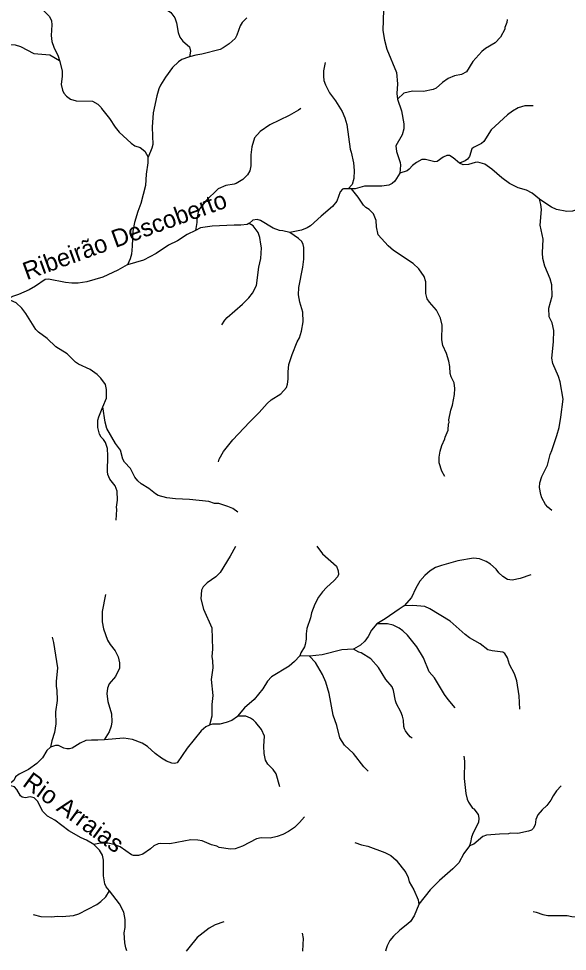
# Model space of a CAD drawing. Extents: x 500 to 555.2, y 9115.7 to 9171.
# Drawn here: x 528.19 to 534.42, y 9115.69 to 9126.27 of the extents above; entities that cross this region are included whole.
import ezdxf
from ezdxf.enums import TextEntityAlignment as Align

# ---------------------------------------------------------------- set-up
doc = ezdxf.new("R2010")
doc.units = 0
doc.header["$LTSCALE"] = 0.064
doc.layers.add('61', color=7, linetype='Continuous')
doc.layers.add('7', color=7, linetype='Continuous', lineweight=25)

msp = doc.modelspace()

# ---------------------------------------------------------------- linework, layer by layer
at = {"layer": '7'}
msp.add_line((531.9688, 9124.34), (531.9304, 9124.3404), dxfattribs=at)
for points in [[(529.3673, 9127.1028), (529.4063, 9127.1229), (529.4402, 9127.1229), (529.4792, 9127.1064), (529.5026, 9127.0847), (529.516, 9127.0636), (529.5298, 9127.004), (529.523, 9126.8054), (529.538, 9126.7218), (529.5514, 9126.6812), (529.5843, 9126.6248), (529.6227, 9126.5758), (529.687, 9126.5131), (529.7188, 9126.494), (529.7656, 9126.4471), (529.9201, 9126.339), (529.9628, 9126.2798), (529.9841, 9126.2226), (530.0006, 9126.1144), (530.0201, 9126.0623), (530.056, 9126.0162), (530.1293, 9125.9499), (530.1415, 9125.9017), (530.1322, 9125.8388)], [(527.3124, 9126.8729), (527.3376, 9126.8303), (527.3752, 9126.7879), (527.4594, 9126.7168), (527.5199, 9126.6335), (527.6458, 9126.514), (527.6924, 9126.4299), (527.7599, 9126.3524), (527.8218, 9126.305), (527.8558, 9126.2711), (527.8955, 9126.2143), (527.9421, 9126.1666), (527.9587, 9126.1564), (527.9813, 9126.129), (528.009, 9126.0495), (528.0386, 9126.0066), (528.0876, 9125.9786), (528.1531, 9125.9727), (528.2133, 9125.9546), (528.3623, 9125.877), (528.544, 9125.86), (528.653, 9125.7947)], [(528.6852, 9126.8448), (528.6686, 9126.8065), (528.633, 9126.7709), (528.5477, 9126.7037), (528.4229, 9126.5503), (528.4093, 9126.5199), (528.4031, 9126.4752), (528.416, 9126.4251), (528.4241, 9126.4208), (528.4489, 9126.385), (528.5422, 9126.2948), (528.5653, 9126.2461), (528.5682, 9126.1995), (528.5605, 9126.0782), (528.5687, 9126.0126), (528.5914, 9125.9477), (528.6392, 9125.8451), (528.653, 9125.7947)], [(532.4206, 9126.6912), (532.4179, 9126.6374), (532.3516, 9126.4503), (532.335, 9126.3716), (532.3266, 9126.1347), (532.3431, 9126.0284), (532.3707, 9125.9247), (532.4793, 9125.6602), (532.4904, 9125.5296), (532.4842, 9125.4203), (532.494, 9125.3578)], [(530.781, 9126.2793), (530.73, 9126.227), (530.7073, 9126.1892), (530.6694, 9126.0843), (530.6476, 9126.0468), (530.581, 9125.9858), (530.514, 9125.9389), (530.4795, 9125.9225), (530.2696, 9125.8667), (530.2019, 9125.8579), (530.1322, 9125.8388)], [(533.7383, 9126.2622), (533.7351, 9126.2273), (533.7124, 9126.1712), (533.7105, 9126.1512), (533.6628, 9126.0591), (533.6027, 9125.9963), (533.4906, 9125.9303), (533.4486, 9125.8994), (533.3474, 9125.7839), (533.2762, 9125.6683), (533.2193, 9125.6373), (533.1402, 9125.6206), (533.0676, 9125.5934), (533.0015, 9125.5473), (532.9294, 9125.4802), (532.8961, 9125.465), (532.7859, 9125.4452), (532.6638, 9125.4482), (532.565, 9125.4239), (532.494, 9125.3578)], [(528.653, 9125.7947), (528.6848, 9125.6786), (528.685, 9125.6197), (528.6754, 9125.5238), (528.6899, 9125.4589), (528.7048, 9125.4255), (528.7337, 9125.3909), (528.7803, 9125.3584), (528.844, 9125.3384), (529.0301, 9125.3332), (529.0919, 9125.299), (529.1273, 9125.2632), (529.1299, 9125.2519), (529.221, 9125.1389), (529.2867, 9125.0389), (529.3335, 9124.982), (529.4684, 9124.8577), (529.5113, 9124.8286), (529.5702, 9124.8073), (529.6245, 9124.7678), (529.6599, 9124.6991)], [(530.1322, 9125.8388), (530.119, 9125.8352), (530.0427, 9125.8055), (530.004, 9125.7797), (529.9362, 9125.7152), (529.8577, 9125.6049), (529.8029, 9125.5155), (529.7838, 9125.474), (529.7597, 9125.3966), (529.7189, 9125.202), (529.7087, 9125.0399), (529.7151, 9124.8422), (529.705, 9124.8014), (529.6599, 9124.6991)], [(531.6715, 9125.7733), (531.6524, 9125.678), (531.6508, 9125.6178), (531.6574, 9125.5698), (531.6756, 9125.52), (531.7204, 9125.4307), (531.7873, 9125.3396), (531.8641, 9125.2164), (531.8934, 9125.1434), (531.9151, 9125.0692), (531.9556, 9124.7905), (531.9671, 9124.7569), (531.9916, 9124.6355), (532.0017, 9124.5462), (531.9952, 9124.455), (531.9759, 9124.3902), (531.9304, 9124.3404)], [(532.494, 9125.3578), (532.5381, 9125.2253), (532.5644, 9125.0777), (532.5628, 9125.0193), (532.5447, 9124.9531), (532.4743, 9124.8274), (532.4815, 9124.7633), (532.5234, 9124.6375), (532.5265, 9124.6079), (532.5184, 9124.5188)], [(531.3933, 9125.2506), (531.3696, 9125.2319), (531.2614, 9125.1709), (531.0416, 9125.0668), (530.9337, 9124.9918), (530.8701, 9124.9183), (530.8389, 9124.8152), (530.8257, 9124.724), (530.8272, 9124.5987), (530.8159, 9124.5451), (530.7908, 9124.4982), (530.7363, 9124.444), (530.6614, 9124.4), (530.6386, 9124.3921), (530.5438, 9124.3785), (530.458, 9124.3387), (530.3151, 9124.2028), (530.2468, 9124.1158), (530.2306, 9124.0764), (530.214, 9123.9925), (530.2154, 9123.9584), (530.1999, 9123.8665)], [(534.0337, 9125.2824), (533.938, 9125.2827), (533.8618, 9125.2581), (533.7963, 9125.222), (533.7405, 9125.1793), (533.5558, 9125.0094), (533.471, 9124.876), (533.4477, 9124.8522), (533.3535, 9124.8079), (533.3375, 9124.7925), (533.3092, 9124.7077), (533.2876, 9124.6742), (533.2615, 9124.6561), (533.1973, 9124.6298)], [(529.6599, 9124.6991), (529.6595, 9124.6983), (529.656, 9124.6334), (529.6382, 9124.5075), (529.6297, 9124.3783), (529.5792, 9124.1729), (529.5437, 9124.0811), (529.5051, 9123.9584), (529.4872, 9123.86), (529.4813, 9123.6888), (529.4727, 9123.5995), (529.4566, 9123.5466), (529.4269, 9123.4774)], [(533.1973, 9124.6298), (533.1241, 9124.6915), (533.083, 9124.7184), (533.052, 9124.7178), (533.0117, 9124.6984), (532.9407, 9124.6501), (532.9177, 9124.6448), (532.8114, 9124.6709), (532.7694, 9124.6739), (532.7066, 9124.6393), (532.6612, 9124.6036), (532.6265, 9124.5643), (532.601, 9124.545), (532.5184, 9124.5188)], [(534.1046, 9124.2222), (534.0222, 9124.2894), (533.958, 9124.3249), (533.8612, 9124.3513), (533.7623, 9124.3982), (533.6754, 9124.4631), (533.5619, 9124.5621), (533.4829, 9124.6199), (533.4058, 9124.6412), (533.3726, 9124.6383), (533.2969, 9124.6167), (533.2395, 9124.6127), (533.1973, 9124.6298)], [(535.0176, 9124.5847), (535.0228, 9124.5174), (535.0398, 9124.4439), (535.1083, 9124.2903), (535.1053, 9124.2424), (535.0914, 9124.226), (535.0555, 9124.2049), (534.991, 9124.1888), (534.8729, 9124.1984), (534.8106, 9124.2117), (534.6951, 9124.2083), (534.653, 9124.1959), (534.5628, 9124.112), (534.4793, 9124.0855), (534.4156, 9124.0837), (534.2968, 9124.1039), (534.2417, 9124.1299), (534.1072, 9124.2201), (534.1046, 9124.2222)], [(532.5184, 9124.5188), (532.4625, 9124.4249), (532.4325, 9124.4), (532.3927, 9124.3809)], [(532.3927, 9124.3809), (532.3146, 9124.3692), (532.1181, 9124.3708), (532.0124, 9124.3396), (531.9688, 9124.34)], [(531.9304, 9124.3404), (531.8794, 9124.3409), (531.8662, 9124.3363), (531.843, 9124.3056), (531.8032, 9124.1986), (531.7561, 9124.1382), (531.624, 9124.0306), (531.5031, 9123.9213), (531.4656, 9123.8976), (531.4029, 9123.8693), (531.268, 9123.8445)], [(533.028, 9121.0729), (532.9949, 9121.1359), (532.966, 9121.2315), (532.9644, 9121.2932), (532.9756, 9121.3602), (532.9971, 9121.4252), (533.0314, 9121.5013), (533.0346, 9121.5211), (533.0661, 9121.5987), (533.0715, 9121.6715), (533.0775, 9121.6862), (533.0762, 9121.7182), (533.0975, 9121.8266), (533.1171, 9121.8858), (533.1383, 9122.0055), (533.1433, 9122.0726), (533.1351, 9122.1383), (533.1024, 9122.204), (533.092, 9122.2428), (533.086, 9122.3214), (533.0734, 9122.3852), (533.048, 9122.4702), (533.0085, 9122.5597), (532.9958, 9122.6238), (532.999, 9122.7933), (532.9811, 9122.8725), (532.9334, 9122.9617), (532.8556, 9123.0524), (532.8307, 9123.0921), (532.8137, 9123.1531), (532.8135, 9123.2839), (532.794, 9123.3455), (532.7361, 9123.4329), (532.6705, 9123.4902), (532.4458, 9123.6396), (532.3856, 9123.6915), (532.2723, 9123.817), (532.2527, 9123.9072), (532.2493, 9123.9796), (532.2215, 9124.0541), (532.1714, 9124.1047), (532.133, 9124.1281), (532.1078, 9124.1547), (532.0451, 9124.2457), (531.9688, 9124.34)], [(534.2436, 9120.6899), (534.1982, 9120.726), (534.1722, 9120.7583), (534.1327, 9120.8321), (534.1194, 9120.8721), (534.1047, 9120.9513), (534.108, 9121.001), (534.1307, 9121.0749), (534.1946, 9121.2023), (534.2247, 9121.3257), (534.2444, 9121.3699), (534.3014, 9121.538), (534.326, 9121.6298), (534.3472, 9121.7473), (534.3735, 9121.9539), (534.3403, 9122.1496), (534.3211, 9122.2104), (534.2574, 9122.3575), (534.2458, 9122.4165), (534.2619, 9122.6035), (534.2652, 9122.7303), (534.249, 9122.82), (534.2129, 9122.888), (534.2095, 9122.9857), (534.2472, 9123.1225), (534.2456, 9123.2504), (534.2271, 9123.3174), (534.1639, 9123.4631), (534.1413, 9123.548), (534.1374, 9123.6127), (534.1456, 9123.7687), (534.1129, 9123.9256), (534.1259, 9124.1033), (534.1191, 9124.1632), (534.1046, 9124.2222)], [(530.8063, 9123.946), (530.8042, 9123.9442), (530.7837, 9123.9338), (530.7132, 9123.9262), (530.6397, 9123.9278), (530.3871, 9123.9147), (530.2539, 9123.8966), (530.1999, 9123.8665)], [(530.4977, 9122.795), (530.5308, 9122.8505), (530.5595, 9122.8809), (530.7339, 9123.03), (530.8047, 9123.1016), (530.8448, 9123.1551), (530.891, 9123.241), (530.9175, 9123.45), (530.9388, 9123.5489), (530.9486, 9123.6697), (530.9389, 9123.7103), (530.9306, 9123.7884), (530.9092, 9123.8442), (530.8523, 9123.9192), (530.8063, 9123.946)], [(531.268, 9123.8445), (531.1889, 9123.8636), (531.1521, 9123.8672), (531.0814, 9123.8927), (530.9353, 9123.9786), (530.8995, 9123.9915), (530.8492, 9123.9821), (530.8063, 9123.946)], [(530.1999, 9123.8665), (530.1056, 9123.8195), (529.9938, 9123.7492), (529.8929, 9123.7001), (529.7519, 9123.6067), (529.6075, 9123.5311), (529.4269, 9123.4774)], [(530.4587, 9121.2428), (530.4668, 9121.2706), (530.516, 9121.3573), (530.6225, 9121.4905), (530.8112, 9121.6908), (530.9228, 9121.7991), (531.0115, 9121.9041), (531.059, 9121.9434), (531.1668, 9122.0136), (531.2317, 9122.0848), (531.2446, 9122.1233), (531.252, 9122.1797), (531.2505, 9122.2623), (531.2603, 9122.3444), (531.2963, 9122.4593), (531.3549, 9122.6011), (531.3801, 9122.6485), (531.4029, 9122.7249), (531.4211, 9122.8296), (531.4175, 9122.9393), (531.3817, 9123.0541), (531.3686, 9123.1362), (531.3734, 9123.2196), (531.4173, 9123.452), (531.4276, 9123.5397), (531.4293, 9123.6735), (531.4224, 9123.707), (531.4057, 9123.7409), (531.3685, 9123.7752), (531.268, 9123.8445)], [(529.4269, 9123.4774), (529.4242, 9123.4766), (529.3185, 9123.4177), (529.1482, 9123.3377), (528.9651, 9123.2826), (528.8667, 9123.2702), (528.796, 9123.2685), (528.7246, 9123.2747), (528.5316, 9123.3142), (528.4905, 9123.3111), (528.384, 9123.2332), (528.3101, 9123.194), (528.1911, 9123.1411), (528.123, 9123.1183), (528.0692, 9123.0883)], [(529.1473, 9121.8661), (529.1887, 9121.9651), (529.1903, 9122.0613), (529.1754, 9122.1185), (529.1234, 9122.1918), (529.0842, 9122.2325), (529.0032, 9122.2891), (528.8694, 9122.3485), (528.8366, 9122.3724), (528.7418, 9122.4667), (528.6151, 9122.5447), (528.5158, 9122.639), (528.4173, 9122.7129), (528.385, 9122.7436), (528.2717, 9122.9256), (528.2264, 9122.9858), (528.1645, 9123.0473), (528.0692, 9123.0883)], [(529.2999, 9120.5774), (529.3066, 9120.6982), (529.3035, 9120.7249), (529.3133, 9120.8058), (529.3083, 9120.9086), (529.2886, 9120.9671), (529.2278, 9121.0447), (529.2039, 9121.0971), (529.2002, 9121.1317), (529.2051, 9121.3075), (529.1983, 9121.3942), (529.1752, 9121.4598), (529.1533, 9121.4942), (529.1274, 9121.5216), (529.1097, 9121.5549), (529.0919, 9121.6319), (529.0919, 9121.7151), (529.0996, 9121.752), (529.1473, 9121.8661)], [(530.6789, 9120.671), (530.6215, 9120.7115), (530.5654, 9120.7355), (530.4637, 9120.7668), (530.4149, 9120.7687), (530.351, 9120.7899), (530.1291, 9120.8129), (529.971, 9120.8195), (529.8726, 9120.8343), (529.7748, 9120.8605), (529.7441, 9120.8778), (529.6687, 9120.9379), (529.5838, 9120.9906), (529.5439, 9121.0235), (529.5089, 9121.0685), (529.4616, 9121.1662), (529.3937, 9121.2362), (529.3755, 9121.2711), (529.3457, 9121.3744), (529.2916, 9121.4483), (529.193, 9121.6211), (529.1738, 9121.6894), (529.1473, 9121.8661)], [(530.6524, 9120.2812), (530.5929, 9120.1705), (530.4799, 9119.9835), (530.4305, 9119.9346), (530.3325, 9119.8689), (530.2861, 9119.8222), (530.2681, 9119.7863), (530.2583, 9119.6872), (530.2879, 9119.5691), (530.3826, 9119.3568), (530.3909, 9119.1136), (530.3845, 9119.0334), (530.3927, 9118.9809), (530.3959, 9118.9022), (530.3779, 9118.771), (530.3959, 9118.5887), (530.383, 9118.4876), (530.3845, 9118.3539), (530.3569, 9118.2536)], [(531.576, 9120.2833), (531.6423, 9120.1979), (531.8, 9120.0568), (531.8197, 9120.0053), (531.8213, 9119.9628), (531.8118, 9119.934), (531.772, 9119.8944), (531.6853, 9119.8156), (531.6405, 9119.766), (531.5965, 9119.7051), (531.5518, 9119.6242), (531.5163, 9119.5285), (531.5049, 9119.4701), (531.4638, 9119.3498), (531.4539, 9119.2907), (531.4537, 9119.2302), (531.4455, 9119.1687), (531.4356, 9119.1396), (531.3933, 9119.0724), (531.3816, 9119.0382)], [(534.0045, 9119.9574), (533.8843, 9119.9188), (533.794, 9119.8979), (533.741, 9119.9042), (533.6871, 9119.9378), (533.6425, 9119.9825), (533.6129, 9120.0236), (533.5477, 9120.0796), (533.4977, 9120.1091), (533.4238, 9120.1385), (533.3567, 9120.1468), (533.1757, 9120.1157), (532.9926, 9120.0649), (532.9237, 9120.0402), (532.863, 9120.0042), (532.8034, 9119.9497), (532.7457, 9119.887), (532.6996, 9119.8086), (532.6493, 9119.7003), (532.5674, 9119.6083)], [(529.1773, 9119.7335), (529.138, 9119.5439), (529.1395, 9119.4258), (529.1542, 9119.3471), (529.2012, 9119.2185), (529.2317, 9119.1688), (529.2866, 9119.0977), (529.3192, 9119.0296), (529.3378, 9118.9581), (529.3362, 9118.8978), (529.2895, 9118.8063), (529.2174, 9118.7212), (529.2001, 9118.6734), (529.192, 9118.609), (529.2017, 9118.5204), (529.2443, 9118.3826), (529.2477, 9118.2901), (529.2405, 9118.2419), (529.217, 9118.1766), (529.1632, 9118.087)], [(532.5674, 9119.6083), (532.5127, 9119.5673), (532.3511, 9119.458), (532.2569, 9119.4023)], [(533.88, 9118.4326), (533.8748, 9118.5866), (533.8487, 9118.7554), (533.8189, 9118.8352), (533.7653, 9118.941), (533.7404, 9119.0152), (533.709, 9119.0646), (533.6872, 9119.0791), (533.5678, 9119.0943), (533.5172, 9119.1091), (533.4304, 9119.1742), (533.3113, 9119.2449), (533.2599, 9119.2826), (533.0913, 9119.433), (532.8607, 9119.5731), (532.8022, 9119.599), (532.665, 9119.6121), (532.5674, 9119.6083)], [(532.2569, 9119.4023), (532.1953, 9119.3301), (532.1584, 9119.2599), (532.1199, 9119.2044), (532.0717, 9119.1587), (531.9913, 9119.1149)], [(533.1487, 9118.4485), (533.066, 9118.5449), (533.0276, 9118.5992), (532.9111, 9118.7911), (532.8534, 9118.8573), (532.7871, 9119.0156), (532.7103, 9119.1431), (532.6057, 9119.2738), (532.5517, 9119.3231), (532.5107, 9119.3522), (532.442, 9119.3889), (532.3797, 9119.4006), (532.2569, 9119.4023)], [(528.5723, 9119.2506), (528.5865, 9119.1896), (528.6308, 9118.9042), (528.6162, 9118.7474), (528.6176, 9118.6926), (528.626, 9118.651), (528.6277, 9118.5305), (528.6081, 9118.403), (528.6129, 9118.2678), (528.5964, 9118.1689), (528.5682, 9118.0763), (528.5512, 9118.0022)], [(531.9913, 9119.1149), (531.9895, 9119.1139), (531.8601, 9119.1069), (531.6376, 9119.0513), (531.4945, 9119.0363)], [(532.6573, 9118.1062), (532.6375, 9118.1189), (532.6008, 9118.1619), (532.5841, 9118.188), (532.5726, 9118.2114), (532.5643, 9118.2383), (532.5588, 9118.3092), (532.5482, 9118.3547), (532.5297, 9118.4022), (532.4797, 9118.4932), (532.4679, 9118.5292), (532.4484, 9118.6459), (532.4311, 9118.6876), (532.361, 9118.7696), (532.277, 9118.9056), (532.1882, 9119.0059), (532.0804, 9119.0741), (532.0537, 9119.0811), (531.9913, 9119.1149)], [(531.3816, 9119.0382), (531.3234, 9118.9733), (531.2632, 9118.921), (531.0633, 9118.8001), (531.0177, 9118.7527), (530.9643, 9118.6654), (530.8645, 9118.544), (530.7568, 9118.4509), (530.6768, 9118.3541)], [(531.4945, 9119.0363), (531.4934, 9119.0362), (531.3816, 9119.0382)], [(532.1609, 9117.7296), (532.1112, 9117.7789), (531.991, 9117.9303), (531.889, 9118.024), (531.8384, 9118.1085), (531.8047, 9118.2481), (531.761, 9118.367), (531.7179, 9118.6116), (531.6784, 9118.7402), (531.6411, 9118.8258), (531.5612, 9118.9649), (531.4945, 9119.0363)], [(530.6768, 9118.3541), (530.674, 9118.3508), (530.6097, 9118.3069), (530.5467, 9118.2808), (530.4769, 9118.2636), (530.3933, 9118.2621), (530.3638, 9118.2564), (530.3569, 9118.2536)], [(531.1575, 9117.5543), (531.1142, 9117.6996), (531.0811, 9117.7493), (531.0207, 9117.811), (530.9953, 9117.8534), (530.9766, 9117.9326), (530.975, 9118.0159), (530.9814, 9118.1285), (530.9486, 9118.2016), (530.8851, 9118.2832), (530.8575, 9118.3089), (530.8234, 9118.3307), (530.7693, 9118.3541), (530.6768, 9118.3541)], [(530.3569, 9118.2536), (530.315, 9118.2348), (530.2626, 9118.1898), (530.104, 9117.9932), (529.99, 9117.8258), (529.9612, 9117.8179), (529.9284, 9117.8211), (529.87, 9117.8436), (529.8114, 9117.8773), (529.742, 9117.9305), (529.6545, 9118.0096), (529.5934, 9118.0498), (529.4823, 9118.0884), (529.3845, 9118.1031), (529.1632, 9118.087)], [(529.1632, 9118.087), (529.089, 9118.0816), (529.0197, 9118.0834), (528.9556, 9118.0771), (528.8899, 9118.048), (528.798, 9117.9923), (528.7678, 9117.9837), (528.7383, 9117.9835), (528.7023, 9117.993), (528.6433, 9118.0228), (528.6089, 9118.0225), (528.5512, 9118.0022)], [(528.5512, 9118.0022), (528.5098, 9117.9641), (528.4615, 9117.8829), (528.3974, 9117.8158), (528.3026, 9117.7499), (528.1958, 9117.6976), (528.1562, 9117.6642), (528.1349, 9117.625), (528.1029, 9117.5974), (528.0666, 9117.5916)], [(533.2452, 9117.8998), (533.2533, 9117.8453), (533.2501, 9117.6459), (533.2663, 9117.4772), (533.2835, 9117.4138), (533.299, 9117.3787), (533.3448, 9117.3086), (533.3573, 9117.3018), (533.4069, 9117.2395), (533.4173, 9117.1978), (533.4108, 9117.1491), (533.3503, 9117.031), (533.3323, 9116.9818), (533.3226, 9116.9218), (533.3109, 9116.881)], [(529.0429, 9116.8996), (528.962, 9116.9461), (528.9024, 9116.9729), (528.7619, 9117.0543), (528.6003, 9117.1727), (528.5172, 9117.2211), (528.467, 9117.2715), (528.4037, 9117.3901), (528.3685, 9117.4271), (528.3205, 9117.4372), (528.2684, 9117.4274), (528.2328, 9117.4353), (528.2103, 9117.4512), (528.1708, 9117.5213), (528.1449, 9117.5509), (528.0985, 9117.5651), (528.0666, 9117.5916)], [(534.3515, 9117.5653), (534.299, 9117.5066), (534.2593, 9117.4518), (534.2339, 9117.4017), (534.187, 9117.3393), (534.1338, 9117.2924), (534.0857, 9117.2365), (534.0617, 9117.1801), (534.0538, 9117.1195), (534.0337, 9117.0813), (534.0146, 9117.0621), (533.9793, 9117.0484), (533.8582, 9117.0232), (533.7696, 9117.0255), (533.7508, 9117.0173), (533.6514, 9117.0156), (533.5037, 9117.0039), (533.4622, 9116.9887), (533.3591, 9116.9015), (533.3109, 9116.881)], [(531.435, 9117.2113), (531.3813, 9117.1481), (531.3223, 9117.0924), (531.2565, 9117.0448), (531.192, 9117.011), (531.1278, 9116.9883), (531.0471, 9116.9683), (530.9427, 9116.9746), (530.8907, 9116.9634), (530.7329, 9116.8791), (530.65, 9116.8502), (530.5944, 9116.8467), (530.467, 9116.864), (530.44, 9116.8779), (530.3806, 9116.8929), (530.2748, 9116.9389), (530.2251, 9116.9482), (530.1449, 9116.9516), (529.9087, 9116.9058), (529.8044, 9116.9106), (529.7769, 9116.9072), (529.7267, 9116.8827), (529.6861, 9116.8475), (529.601, 9116.7896), (529.5504, 9116.7718), (529.4955, 9116.7731), (529.4721, 9116.7822), (529.3451, 9116.871), (529.2748, 9116.8976), (529.2034, 9116.912), (529.1216, 9116.9123), (529.0429, 9116.8996)], [(529.2213, 9116.3721), (529.1859, 9116.4186), (529.1709, 9116.4524), (529.1527, 9116.5423), (529.154, 9116.7202), (529.1424, 9116.7784), (529.1091, 9116.8355), (529.0429, 9116.8996)], [(532.008, 9116.9189), (532.0843, 9116.8942), (532.157, 9116.8796), (532.3473, 9116.8084), (532.4174, 9116.7719), (532.4765, 9116.7212), (532.5858, 9116.5792), (532.6117, 9116.5244), (532.6251, 9116.4728), (532.6761, 9116.3836), (532.7267, 9116.2693), (532.7332, 9116.218)], [(533.3109, 9116.881), (533.2464, 9116.797), (533.1883, 9116.6914), (533.122, 9116.622), (532.9704, 9116.4896), (532.8623, 9116.385), (532.734, 9116.22), (532.7332, 9116.218)], [(528.3563, 9116.1047), (528.4446, 9116.0809), (528.5693, 9116.0759), (528.6293, 9116.0839), (528.6852, 9116.0808), (528.8147, 9116.0907), (528.8759, 9116.1121), (529.0803, 9116.2185), (529.1258, 9116.2493), (529.1797, 9116.3048), (529.2213, 9116.3721)], [(529.4179, 9115.6895), (529.4088, 9115.7264), (529.3953, 9115.7812), (529.3905, 9115.8971), (529.3986, 9115.9577), (529.4001, 9116.0462), (529.3839, 9116.1303), (529.3346, 9116.2234), (529.2213, 9116.3721)], [(532.7332, 9116.218), (532.6799, 9116.0871), (532.6382, 9116.0256), (532.6109, 9115.9962), (532.5202, 9115.9265), (532.4483, 9115.8577), (532.407, 9115.8067), (532.3745, 9115.7483), (532.3643, 9115.7133), (532.3568, 9115.6875)], [(534.0323, 9116.1368), (534.0675, 9116.1301), (534.1434, 9116.1023), (534.2006, 9116.0908), (534.4195, 9116.0904), (534.4726, 9116.0808), (534.6471, 9116.0756), (534.7647, 9116.0642), (534.8913, 9116.0304), (534.9896, 9115.9839), (535.0527, 9115.9412), (535.1046, 9115.8925), (535.148, 9115.7865), (535.1709, 9115.7002), (535.1748, 9115.6854)], [(530.5206, 9116.0194), (530.4233, 9115.987), (530.3537, 9115.9497), (530.2175, 9115.8416), (530.1237, 9115.7264), (530.0933, 9115.6891)], [(531.4097, 9115.8899), (531.4219, 9115.8323), (531.4184, 9115.7626), (531.4132, 9115.6882)]]:
    msp.add_lwpolyline(points, dxfattribs=at)

# ---------------------------------------------------------------- texts
at = {"layer": '61'}
for s, rotation, p in [('Ribeirão Descoberto', 19.952, (529.4288, 9123.7183)), ('Rio Arraias', 323.918, (528.7582, 9117.1816))]:
    msp.add_text(s, height=0.2, rotation=rotation, dxfattribs=at).set_placement(p, align=Align.CENTER)

doc.saveas('drawing.dxf')
